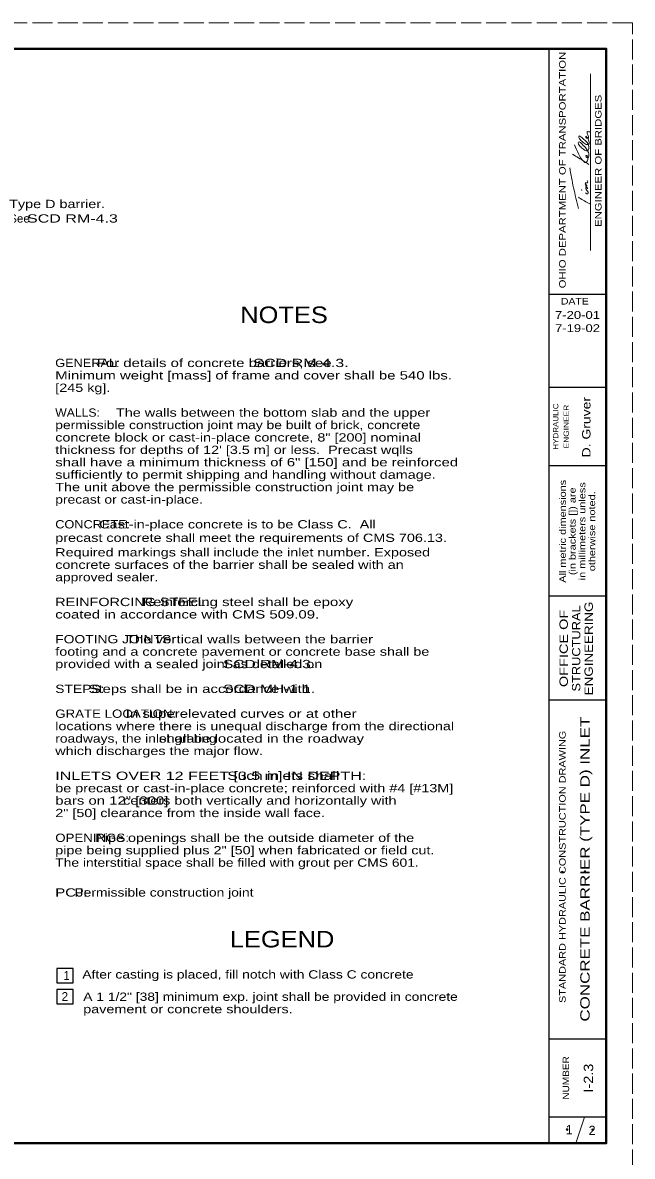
# Model space of a CAD drawing. Extents: x -1431.2 to -1397.2, y -1045.1 to -1001.1.
# Drawn here: x -1408.95 to -1397.25, y -1022.83 to -1001.08 of the extents above; entities that cross this region are included whole.
import ezdxf
from ezdxf.enums import TextEntityAlignment as Align

# ---------------------------------------------------------------- set-up
doc = ezdxf.new("R2010")
doc.units = 0
doc.header["$LTSCALE"] = 0.064
doc.header["$PDMODE"] = 32
doc.header["$PDSIZE"] = 0.032
doc.linetypes.add('LONG_DASHED', pattern=[7.5, 6, -1.5])
doc.layers.add('1', color=7, linetype='Continuous', lineweight=13)

msp = doc.modelspace()

# ---------------------------------------------------------------- linework, layer by layer
at = {"layer": '1', "lineweight": 25}
for p, q in [((-1429.24575, -1001.57983), (-1397.74575, -1001.57983)), ((-1398.84575, -1022.57983), (-1398.84575, -1001.57983)), ((-1397.74575, -1001.57983), (-1397.74575, -1022.57983)), ((-1397.74575, -1006.29567), (-1398.84575, -1006.29567)), ((-1397.74575, -1008.07983), (-1398.84575, -1008.07983)), ((-1397.74575, -1009.57983), (-1398.84575, -1009.57983)), ((-1397.74575, -1012.07983), (-1398.84575, -1012.07983)), ((-1397.74575, -1014.07983), (-1398.84575, -1014.07983)), ((-1397.74575, -1020.57983), (-1398.84575, -1020.57983)), ((-1397.74575, -1022.07983), (-1398.84575, -1022.07983))]:
    msp.add_line(p, q, dxfattribs=at)
at = {"layer": '1'}
for p, q in [((-1398.047, -1005.44883), (-1398.047, -1002.05875)), ((-1398.2145, -1004.29792), (-1398.22467, -1004.27867)), ((-1398.32908, -1022.57983), (-1398.16242, -1022.07983))]:
    msp.add_line(p, q, dxfattribs=at)
at = {"layer": '1', "linetype": 'LONG_DASHED'}
msp.add_lwpolyline([(-1431.24575, -1023.07983), (-1397.24575, -1023.07983), (-1397.24575, -1001.07983), (-1431.24575, -1001.07983)], close=True, dxfattribs=at)
at = {"layer": '1', "lineweight": 25}
msp.add_lwpolyline([(-1397.74575, -1022.57983), (-1429.24575, -1022.57983), (-1429.24575, -1001.57983)], dxfattribs=at)
at = {"layer": '1', "lineweight": 40}
msp.add_lwpolyline([(-1429.24575, -1001.57983), (-1397.74575, -1001.57983), (-1397.74575, -1022.57983), (-1429.24575, -1022.57983)], close=True, dxfattribs=at)
at = {"layer": '1', "lineweight": 25}
for points in [[(-1408.2975, -1019.22517), (-1408.2975, -1019.503), (-1407.98025, -1019.503), (-1407.98025, -1019.22517)], [(-1408.2975, -1019.62725), (-1408.2975, -1019.90525), (-1407.98025, -1019.90525), (-1407.98025, -1019.62725)]]:
    msp.add_lwpolyline(points, close=True, dxfattribs=at)
at = {"layer": '1'}
for points in [[(-1398.35392, -1003.42283), (-1398.17075, -1003.75117), (-1398.15558, -1003.76175), (-1398.14542, -1003.76175), (-1398.1135, -1003.73808), (-1398.09842, -1003.70392), (-1398.10342, -1003.65267), (-1398.12033, -1003.63083), (-1398.13383, -1003.63083), (-1398.13558, -1003.64383), (-1398.12542, -1003.659), (-1398.11192, -1003.66742), (-1398.09683, -1003.66742), (-1398.08167, -1003.64583), (-1398.07825, -1003.6265), (-1398.0885, -1003.57117), (-1398.17075, -1003.45075), (-1398.21625, -1003.40608), (-1398.25317, -1003.3715), (-1398.27833, -1003.36933), (-1398.27658, -1003.40792), (-1398.25142, -1003.44667), (-1398.18417, -1003.509), (-1398.14208, -1003.53442), (-1398.10842, -1003.53892), (-1398.08508, -1003.51292), (-1398.07825, -1003.47875), (-1398.08333, -1003.453), (-1398.1135, -1003.37983), (-1398.14375, -1003.34783), (-1398.20433, -1003.29442), (-1398.233, -1003.26858), (-1398.2665, -1003.25333), (-1398.26992, -1003.28133), (-1398.25983, -1003.30717), (-1398.20267, -1003.36708), (-1398.132, -1003.41433), (-1398.08, -1003.412), (-1398.08167, -1003.35433), (-1398.0935, -1003.31142), (-1398.10683, -1003.28567), (-1398.117, -1003.27492), (-1398.14042, -1003.25992), (-1398.13867, -1003.277), (-1398.10342, -1003.2985), (-1398.0885, -1003.28775), (-1398.10158, -1003.23408), (-1398.11017, -1003.20617), (-1398.1135, -1003.1935), (-1398.1135, -1003.18067), (-1398.1135, -1003.172), (-1398.0885, -1003.17417), (-1398.06308, -1003.17417)], [(-1398.39275, -1003.60508), (-1398.169, -1003.74258), (-1398.08333, -1003.79825)], [(-1398.2765, -1004.64208), (-1398.37517, -1004.24683), (-1398.44642, -1003.8645)], [(-1398.14542, -1004.34317), (-1398.13717, -1004.35383), (-1398.1, -1004.36675), (-1398.09525, -1004.33433), (-1398.12033, -1004.29792), (-1398.13558, -1004.26167), (-1398.13558, -1004.24242), (-1398.12033, -1004.24867), (-1398.11017, -1004.2595), (-1398.1, -1004.26383), (-1398.12367, -1004.23167), (-1398.13558, -1004.21667), (-1398.13867, -1004.19933), (-1398.11525, -1004.20592), (-1398.12367, -1004.19725), (-1398.14883, -1004.16942), (-1398.13867, -1004.15425), (-1398.12192, -1004.15225), (-1398.1135, -1004.15425), (-1398.10342, -1004.13292), (-1398.11017, -1004.105)], [(-1398.06133, -1004.55767), (-1398.2665, -1004.43767), (-1398.28208, -1004.42725)]]:
    msp.add_spline(points, degree=3, dxfattribs=at)
for p in [(-1398.58833, -1017.37383), (-1398.1555, -1017.3665), (-1398.49767, -1022.31608), (-1398.00925, -1022.31708)]:
    msp.add_point(p, dxfattribs=at)

# ---------------------------------------------------------------- texts
for s, height, width, p in [('OHIO DEPARTMENT OF TRANSPORTATION', 0.125, 1.3, (-1398.52583, -1003.90758)), ('ENGINEER OF BRIDGES', 0.125, 1.3, (-1397.8375, -1003.73079)), ('D. Gruver', 0.16, 1.25, (-1398.04958, -1008.84058)), ('HYDRAULIC', 0.1, 1.15, (-1398.66667, -1008.82875)), ('ENGINEER', 0.1, 1.2, (-1398.46575, -1008.82871)), ('All metric dimensions', 0.125, 1.25, (-1398.52192, -1010.83775)), ('(in brackets []) are', 0.125, 1.25, (-1398.33442, -1010.83775)), ('in millimeters unless', 0.125, 1.25, (-1398.14692, -1010.83771)), ('otherwise noted.', 0.125, 1.25, (-1397.95942, -1010.83775)), ('ENGINEERING', 0.16, 1.2, (-1398.004, -1013.08529)), ('OFFICE OF', 0.16, 1.3, (-1398.484, -1013.08537)), ('STRUCTURAL', 0.16, 1.15, (-1398.244, -1013.08537)), ('CONCRETE BARRIER (TYPE D) INLET', 0.18, 1.35, (-1398.0655, -1017.31967)), ('STANDARD HYDRAULIC CONSTRUCTION DRAWING', 0.125, 1.25, (-1398.52583, -1017.27579)), ('NUMBER', 0.125, 1.15, (-1398.45875, -1021.32575)), ('I-2.3', 0.18, 1.15, (-1397.9985, -1021.32946))]:
    msp.add_text(s, height=height, rotation=90, dxfattribs=dict(at, width=width)).set_placement(p, align=Align.CENTER)
for s, height, width, p in [('Type D barrier.', 0.1588, 1.3, (-1409.20983, -1004.6375)), ('See', 0.1588, 1.05, (-1409.20983, -1004.91533)), ('    SCD RM-4.3', 0.1588, 1.45, (-1409.20983, -1004.91533)), ('NOTES', 0.3175, 1.15, (-1404.77358, -1006.84308)), ('GENERAL:', 0.1588, 1.15, (-1408.32517, -1007.68725)), ('          For details of concrete barriers, see             ', 0.1588, 1.35, (-1408.32517, -1007.68725)), ('                                            SCD RM-4.3.', 0.1588, 1.45, (-1408.287, -1007.68725)), ('Minimum weight [mass] of frame and cover shall be 540 lbs.', 0.1588, 1.35, (-1408.32517, -1007.92533)), ('[245 kg].', 0.1588, 1.3, (-1408.32517, -1008.1635)), ('WALLS:', 0.1588, 1.1, (-1408.32517, -1008.63983)), ('The walls between the bottom slab and the upper', 0.1588, 1.3, (-1407.15875, -1008.64033)), ('permissible construction joint may be built of brick, concrete', 0.1588, 1.25, (-1408.32517, -1008.878)), ('concrete block or cast-in-place concrete, 8" [200] nominal', 0.1588, 1.3, (-1408.32517, -1009.116)), ("thickness for depths of 12' [3.5 m] or less.  Precast wqlls", 0.1588, 1.3, (-1408.32517, -1009.35417)), ('shall have a minimum thickness of 6" [150] and be reinforced', 0.1588, 1.35, (-1408.32517, -1009.59242)), ('sufficiently to permit shipping and handling without damage.', 0.1588, 1.3, (-1408.32517, -1009.83058)), ('The unit above the permissible construction joint may be', 0.1588, 1.3, (-1408.32517, -1010.06875)), ('precast or cast-in-place.', 0.1588, 1.25, (-1408.32517, -1010.30683)), ('CONCRETE:', 0.1588, 1.15, (-1408.32517, -1010.78317)), ('           Cast-in-place concrete is to be Class C.  All', 0.1588, 1.3, (-1408.32517, -1010.78317)), ('precast concrete shall meet the requirements of CMS 706.13.', 0.1588, 1.3, (-1408.32517, -1011.04167)), ('Required markings shall include the inlet number. Exposed ', 0.1588, 1.3, (-1408.32517, -1011.3205)), ('concrete surfaces of the barrier shall be sealed with an ', 0.1588, 1.3, (-1408.32517, -1011.55867)), ('approved sealer.', 0.1588, 1.25, (-1408.32517, -1011.79683)), ('REINFORCING STEEL:', 0.1588, 1.3, (-1408.32517, -1012.27333)), ('                     Reinforcing steel shall be epoxy', 0.1588, 1.35, (-1408.32517, -1012.27317)), ('coated in accordance with CMS 509.09.', 0.1588, 1.35, (-1408.32517, -1012.51133)), ('FOOTING JOINTS:', 0.1588, 1.25, (-1408.32517, -1012.98775)), ('                 The vertical walls between the barrier', 0.1588, 1.35, (-1408.32517, -1012.98775)), ('footing and a concrete pavement or concrete base shall be', 0.1588, 1.3, (-1408.32517, -1013.22592)), ('provided with a sealed joint as detailed on', 0.1588, 1.3, (-1408.32517, -1013.46408)), ('                                       SCD RM-4.3.', 0.1588, 1.4, (-1408.32517, -1013.46408)), ('STEPS:', 0.1588, 1.25, (-1408.32517, -1013.94033)), ('        Steps shall be in accordance with ', 0.1588, 1.35, (-1408.32517, -1013.94033)), ('                                       SCD MH-1.1.', 0.1588, 1.4, (-1408.32517, -1013.94033)), ('GRATE LOCATION:', 0.1588, 1.2, (-1408.32517, -1014.41667)), ('                 In superelevated curves or at other', 0.1588, 1.35, (-1408.32517, -1014.41667)), ('locations where there is unequal discharge from the directional', 0.1588, 1.3, (-1408.32517, -1014.65483)), ('roadways, the inlet grating', 0.1588, 1.25, (-1408.32517, -1014.89292)), ('                         shall be located in the roadway', 0.1588, 1.35, (-1408.32517, -1014.89292)), ('which discharges the major flow.', 0.1588, 1.3, (-1408.32517, -1015.13108)), ('INLETS OVER 12 FEET [3.5 m] IN DEPTH:', 0.1588, 1.45, (-1408.32517, -1015.60742)), ('                                        Such inlets shall', 0.1588, 1.4, (-1408.32517, -1015.60742)), ('be precast or cast-in-place concrete; reinforced with #4 [#13M]', 0.1588, 1.3, (-1408.32517, -1015.84558)), ('bars on 12" [300]', 0.1588, 1.35, (-1408.32517, -1016.08367)), ('                 centers both vertically and horizontally with', 0.1588, 1.3, (-1408.32517, -1016.08367)), ('2" [50] clearance from the inside wall face.', 0.1588, 1.3, (-1408.32517, -1016.32183)), ('OPENINGS:', 0.1588, 1.2, (-1408.32517, -1016.79817)), ('          Pipe openings shall be the outside diameter of the', 0.1588, 1.3, (-1408.32517, -1016.79817)), ('pipe being supplied plus 2" [50] when fabricated or field cut.', 0.1588, 1.3, (-1408.32517, -1017.03633)), ('The interstitial space shall be filled with grout per CMS 601.', 0.1588, 1.25, (-1408.32517, -1017.27442)), ('     Permissible construction joint', 0.1588, 1.25, (-1408.32517, -1017.84667)), ('PCJ: ', 0.1588, 1.35, (-1408.32517, -1017.84667)), ('LEGEND', 0.3175, 1.15, (-1404.97408, -1018.82233)), ('1', 0.1682, 0.95, (-1408.16767, -1019.4445)), ('After casting is placed, fill notch with Class C concrete', 0.1588, 1.25, (-1407.805, -1019.41867)), ('A 1 1/2" [38] minimum exp. joint shall be provided in concrete', 0.1588, 1.25, (-1407.78825, -1019.84658)), ('pavement or concrete shoulders.', 0.1588, 1.3, (-1407.78825, -1020.08475))]:
    msp.add_text(s, height=height, dxfattribs=dict(at, width=width)).set_placement(p)
for s, height, width, p in [('DATE', 0.125, 1.2, (-1398.34904, -1006.48708)), ('7-20-01', 0.15, 1.25, (-1398.29871, -1006.76258)), ('7-19-02', 0.15, 1.25, (-1398.29871, -1007.01567))]:
    msp.add_text(s, height=height, dxfattribs=dict(at, width=width)).set_placement(p, align=Align.CENTER)
msp.add_text('2', height=0.1682, dxfattribs=at).set_placement((-1408.20333, -1019.84825))
for s, p in [('1', (-1398.4579, -1022.40975)), ('2', (-1398.01846, -1022.42233))]:
    msp.add_text(s, height=0.18, dxfattribs=at).set_placement(p, align=Align.CENTER)

doc.saveas('drawing.dxf')
